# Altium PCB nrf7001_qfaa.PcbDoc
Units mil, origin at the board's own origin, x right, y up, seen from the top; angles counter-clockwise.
Board outline 738 x 600 mil, 4 copper layers (Top Layer, Mid-Layer 1, Mid-Layer 2, Bottom Layer), stack 62.315 mil thick; 22 components, 30 nets, 104 pads, 140 vias.
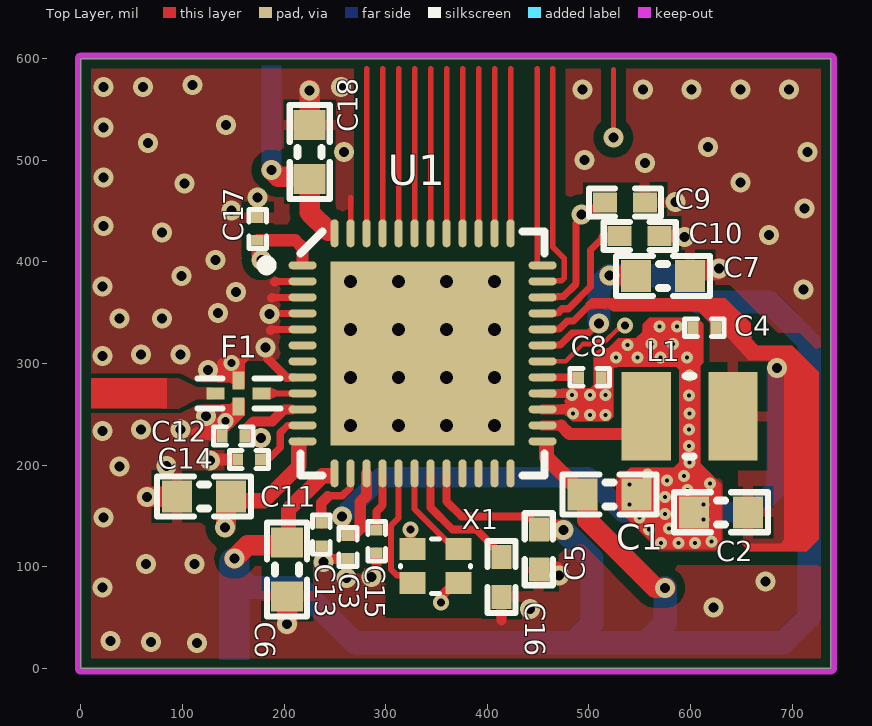
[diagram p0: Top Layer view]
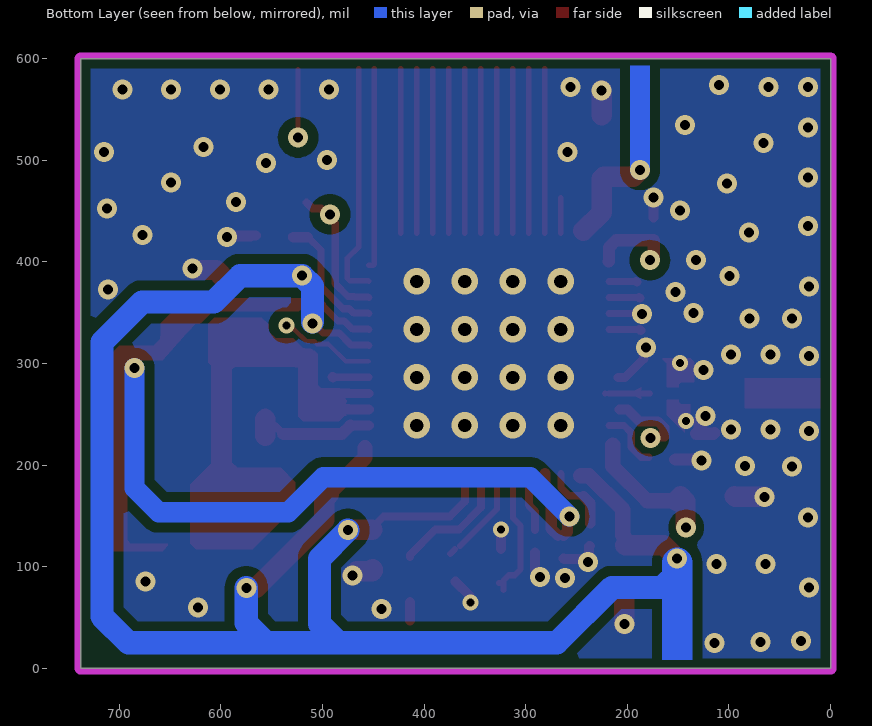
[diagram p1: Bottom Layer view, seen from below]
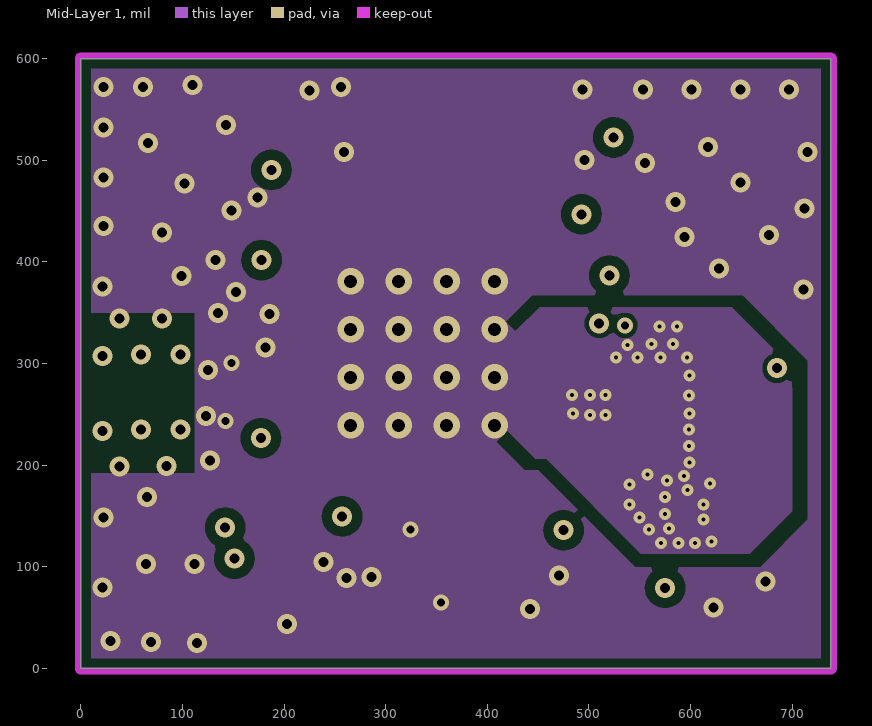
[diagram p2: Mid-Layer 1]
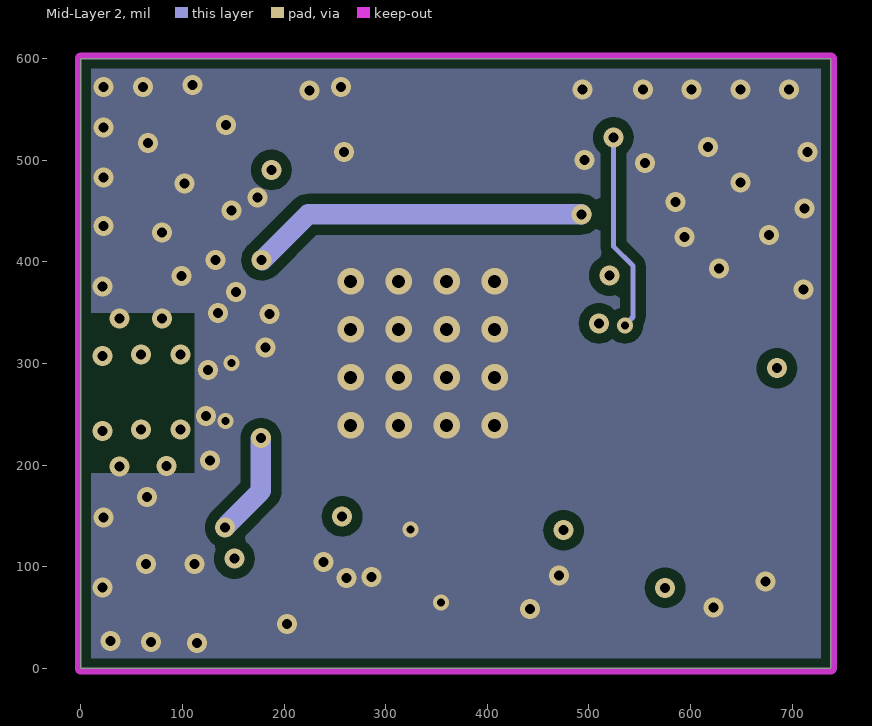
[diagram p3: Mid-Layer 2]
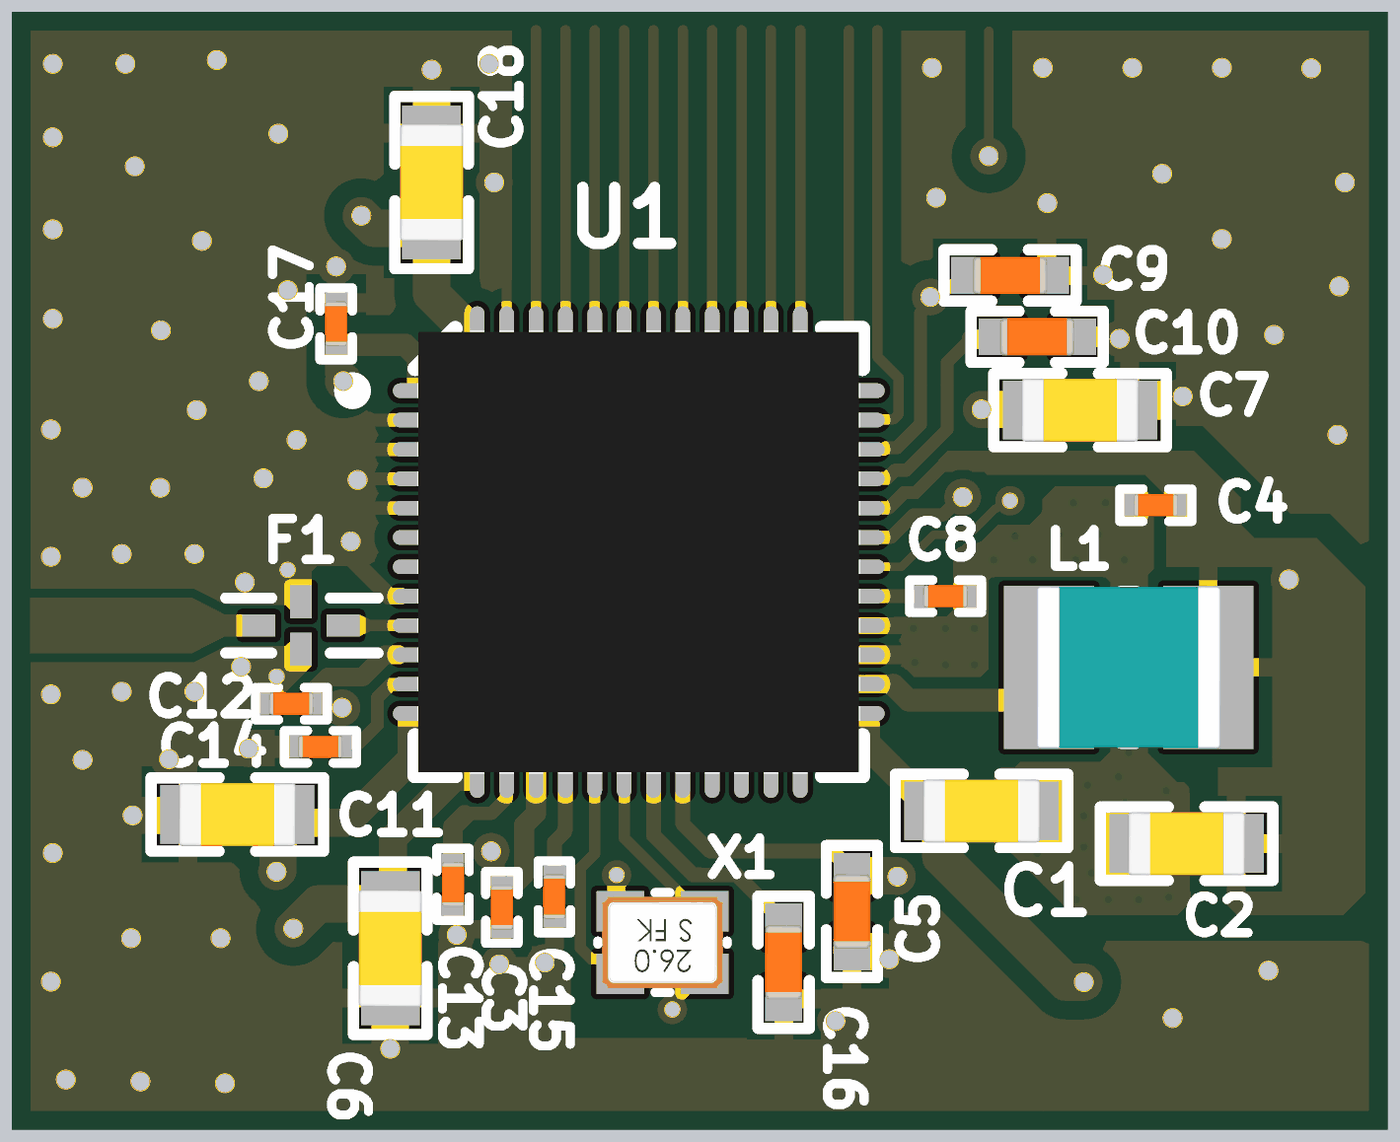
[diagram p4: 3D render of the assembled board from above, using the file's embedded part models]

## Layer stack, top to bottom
Top Solder: solder mask 1.063, Solder Resist, Dk 3.5
Top Layer: signal copper 0.689
Dielectric1: prepreg 3.5, FR-4, Dk 4.2
Mid-Layer 1: signal copper 1.378
Dielectric2: prepreg 51.1811, FR-4, Dk 4.2
Mid-Layer 2: signal copper 1.378
Dielectric3: prepreg 3.5, FR-4, Dk 4.2
Bottom Layer: signal copper 0.689
Bottom Solder: solder mask 1.063, Solder Resist, Dk 3.5

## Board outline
0,0 0,600 738,600 738,0

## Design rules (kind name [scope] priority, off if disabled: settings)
Clearance Clearance_2 [InNet('PALDO') vs OnLayer('Bottom Layer')] p1: gap=10 ignorepadtopadclearanceinfootprint=FALSE except(8: Via-Fill Via-Poly Via-Region)
Clearance Clearance_1 [InNet('ant') vs InNet('GND')] p2: gap=4.76 ignorepadtopadclearanceinfootprint=FALSE except(5: Arc-Arc Arc-Track Arc-Fill Arc-Poly Arc-Region Track-Track Track-Fill Track-Poly Track-Region SMDPad-Fill SMDPad-Poly SMDPad-Region)
Clearance Clearacnce_microvia [AsMM(ViaDiameter) = 0.3 vs AsMM(ViaDiameter) = 0.3] p3: gap=3.94 ignorepadtopadclearanceinfootprint=FALSE
Clearance Polygon_Clearance [(InNamedPolygon('Top_Layer-GND')) or (InNamedPolygon('Bottom_Layer-GND')) or (InNamedPolygon('Mid_Layer_1-GND')) or (InNamedPolygon('Mid_Layer_2-GND'))] p4: gap=10 ignorepadtopadclearanceinfootprint=FALSE except(0: Arc-Hole Track-Hole SMDPad-Hole THPad-Hole Via-Hole Fill-Hole Poly-Hole Region-Hole Text-Hole)
Clearance [All] p5: gap=4.76 ignorepadtopadclearanceinfootprint=FALSE except(5: Arc-Arc Arc-Track Track-Track)
ComponentClearance [All] p1 off: gap=10 collisioncheckmode=3 verticalgap=10 showdistances=FALSE
FabricationTestPointUsage TestPointUsage [All] p1: valid=0 allowmultiple=FALSE
FabricationTestpoint Testpoint [All] p1: side=3 testpointundercomponent=TRUE minsize=40 maxsize=100 preferedsize=60 minholesize=0 maxholesize=40 preferedholesize=32 testpointgrid=1 allowsidetop=TRUE allowsidebottom=TRUE usegrid=TRUE gridtolerance=0.01
Height [All] p1 off: minheight=0 maxheight=1000 prefheight=500
HoleSize [All] p1: absolutevalues=TRUE maxlimit=300 minlimit=3.94 maxpercent=80.000 minpercent=20.000
MinimumAnnularRing [All] p1 off: minimumring=6
PolygonConnect PolygonConnect_1 [isVia and innet(gnd)] p1: connectstyle=Direct reliefconductorwidth=10 reliefentries=4 polygonreliefangle="90 Angle" airgapwidth=10
PolygonConnect [All] p2: connectstyle=Relief reliefconductorwidth=10 reliefentries=4 polygonreliefangle="90 Angle" airgapwidth=10
RoutingVias [All] p1: holewidth=12.01 width=24 viastyle="Through Hole" minholewidth=3.94 minwidth=11.81 maxholewidth=12.01 maxwidth=24.02 useviatemplates=TRUE viatemplateguid#1={03A9E32F-EA80-447D-9B7D-60258545F035} viatemplateguid#2={9F61FF23-C90F-4B7F-A7DC-5F6911D9F630} viatemplateguid#3={EDF5FEF7-A820-4EA2-9A2F-3AF23343353B} viatemplateguid#4={47291F57-6B59-4CD3-85A7-BAD8324BE8B3} viatemplateguid#5={619015CA-C900-4F5D-A376-D984FD50A0EF} viatemplatename#1=v30h10m0 viatemplatename#2=v40h20m0mx0 viatemplatename#3=v50h25m0mx0 viatemplatename#4=v50h25m0mx0_2670034071 viatemplatename#5=v66h33m0mx0_2670034071
SilkToSolderMaskClearance SilkscreenOverComponentPads [IsPad] p1: minsilkscreentomaskgap=10 clearancetoexposedcopper=TRUE
SolderMaskExpansion [IsVia] p1: expansion=3 istentingtop=TRUE
SolderMaskExpansion SolderMaskExpansion_1 [All] p2: expansion=3 istentingtop=FALSE
SupplyNets "Schematic Supply Nets_4" [InNet('VDD_BUCK')] p1: voltage=0.000
SupplyNets "Schematic Supply Nets_3" [InNet('VBAT')] p2: voltage=0.000
SupplyNets "Schematic Supply Nets_2" [InNet('GND')] p3: voltage=0.000
SupplyNets "Schematic Supply Nets_1" [InNet('PWRIOVDD')] p4: voltage=0.000
SupplyNets "Schematic Supply Nets" [InNet('VDDIO')] p5: voltage=0.000
Width [All] p1: maxlimit=100 minlimit=4.5 preferedwidth=6 midlayer1_minwidth=4.92 midlayer4_minwidth=4.92 minimp=50.000000 maximp=50.000000 favimp=50.000000
24 further rules are at their usual default settings.

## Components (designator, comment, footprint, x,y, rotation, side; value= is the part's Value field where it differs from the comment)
C1 "4.7µF" CAPC1608X06L 520.13,171.12 r180 top
C2 "4.7µF" CAPC1608X06L 630.12,153.57 r0 top
C3 "0.22µF" CAPC0603X03L_C 262.9,119.37 r90 top
C4 "0.47µF" CAPC0603X03L_C 613.59,335.17 r0 top
C5 "1.0µF" CAPC1005X04L 450.63,117.17 r90 top
C6 "4.7µF" CAPC1608X06L 203,97.43 r90 top
C7 "2.2µF" CAPC1608X06L 573,386.21 r180 top
C8 "10nF" CAPC0603X03L_C 500.84,286.32 r0 top
C9 "2.2µF" CAPC1005X04L 535.42,458.43 r180 top
C10 "1.0µF" CAPC1005X04L 550,425.52 r0 top
C11 "4.7µF" CAPC1608X06L 121,169.26 r0 top
C12 "100nF" CAPC0603X03L_C 150,228.68 r0 top
C13 "22nF" CAPC0603X03L_C 236.64,131.71 r90 top
C14 "0.47µF" CAPC0603X03L_C 165.53,205.52 r0 top
C15 "2.2µF" CAPC0603X03L_C 291.02,125.04 r90 top
C16 "1.0µF" CAPC1005X04L 414.02,89.94 r90 top
C17 "100nF" CAPC0603X03L_C 174,432.48 r270 top
C18 "2.2µF" CAPC1608X06L 225.18,508.34 r270 top
F1 "LPF1005LL50R2400A" FILTER1005X04L-4pin 155.12,270.63 r180 top
L1 "3.3µH" INDC2520X10N 599.04,248.17 r0 top
U1 "nRF7001 QFAA" QFN40P600X600X60-48N 336.31,310 r0 top locked value=nRF7001-QFAA
X1 "40MHz" BT-XTAL_1612 349.03,100.52 r180 top

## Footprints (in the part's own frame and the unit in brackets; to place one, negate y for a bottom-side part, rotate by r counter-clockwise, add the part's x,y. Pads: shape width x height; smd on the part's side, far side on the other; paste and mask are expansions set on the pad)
BT-XTAL_1612 [mm] "Crystal 1.6 x 1.2 mm"
  rect 0.65x0.55 smd: 1(-0.575,-0.425) 2(0.575,-0.425) 3(0.575,0.425) 4(-0.575,0.425)
  silkscreen extent -0.88,-0.68 0.88,0.68, body extent -0.83,-0.63 0.83,0.63, height 0.41
CAPC0603X03L_C [mm] "Chip Capacitor, 2-Leads, Body 0.6x0.3mm, IPC High Density"
  rect 0.27x0.3 smd mask+0.05: 1(-0.285,0) 2(0.285,0)
  silkscreen extent -0.49,-0.22 0.49,0.22, body extent -0.3,-0.15 0.31,0.15, height 0.3
CAPC1005X04L [mm] "Chip Capacitor, 2-Leads, Body 1.0x0.5mm, IPC High Density"
  rect 0.6x0.5 smd: 1(-0.5,0) 2(0.5,0)
  silkscreen extent -0.9,-0.35 0.9,0.35, body extent -0.51,-0.25 0.51,0.25, height 0.5
CAPC1608X06L [mm] "Chip Capacitor, 2-Leads, Body 1.6x0.8mm, IPC High Density"
  rect 0.75x0.8 smd: 1(-0.675,0) 2(0.675,0)
  silkscreen extent -1.17,-0.5 1.17,0.5, body extent -0.8,-0.43 0.8,0.43, height 0.8
FILTER1005X04L-4pin [mm] "Filter, 4-Leads, Body 1.0x0.5mm."
  rect 0.45x0.3 smd mask+0.08: 1(-0.575,0) 3(0.575,0)
  rect 0.3x0.45 smd mask+0.08: 2(0,-0.325) 4(0,0.325)
  silkscreen extent -1.05,-0.38 1.02,0.38, body extent -0.5,-0.3 0.5,0.3, height 0.36
INDC2520X10N [mm] "Chip Inductor, 2-Leads, Body 2,50x2,00mm, IPC Medium Density"
  rect 1.23x2.22 smd: 1(-1.085,0) 2(1.085,0)
  silkscreen extent -0.1,-1.01 0.1,1.01, body extent -1.25,-1.1 1.25,1.1, height 1.98
QFN40P600X600X60-48N [mm] "QFN, 48-Leads, Body 6.1x6.1mm (max), Pitch 0.40mm, IPC Medium Density"
  oval 0.7x0.2 smd: 1(-3,2.2) 2(-3,1.8) 3(-3,1.4) 4(-3,1) 5(-3,0.6) 6(-3,0.2) 7(-3,-0.2) 8(-3,-0.6) 9(-3,-1) 10(-3,-1.4) 11(-3,-1.8) 12(-3,-2.2) 25(3,-2.2) 26(3,-1.8) 27(3,-1.4) 28(3,-1) 29(3,-0.6) 30(3,-0.2) 31(3,0.2) 32(3,0.6) 33(3,1) 34(3,1.4) 35(3,1.8) 36(3,2.2)
  oval 0.2x0.7 smd: 13(-2.2,-3) 14(-1.8,-3) 15(-1.4,-3) 16(-1,-3) 17(-0.6,-3) 18(-0.2,-3) 19(0.2,-3) 20(0.6,-3) 21(1,-3) 22(1.4,-3) 23(1.8,-3) 24(2.2,-3) 37(2.2,3) 38(1.8,3) 39(1.4,3) 40(1,3) 41(0.6,3) 42(0.2,3) 43(-0.2,3) 44(-0.6,3) 45(-1,3) 46(-1.4,3) 47(-1.8,3) 48(-2.2,3)
  rect 4.6x4.6 smd paste-5: 49(0,0)
  silkscreen extent -4.02,-3.05 3.05,3.05, body extent -3.02,-3.02 3.02,3.02, height 0.86

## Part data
C1 C2 C6 C11: library part C0603-4µ7-25V-X6S-GRM188C81E475KE11, "Capacitor, Ceramic, X6S 0603,±10%, 25V", Manufacturer=Murata, Manufacturer Part Number=GRM188C81E475KE11D, Supplier Part Number 1=490-7199-1-ND
C3: library part C0201-220n-10V-X5R-GRM033R61A224KE90, "Capacitor, Ceramic, X5R 0201, ±10%, 10V", Manufacturer=Murata, Manufacturer Part Number=GRM033R61A224KE90D, Supplier Part Number 1=81-GRM33R61A224KE90D
C4 C14: library part C0201-470n-6.3V-X5R-GRM033R60J474KE90, "Capacitor, Ceramic, X5R 0201,±10%, 6.3V", Manufacturer=Murata, Manufacturer Part Number=GRM033R60J474KE90D, Supplier Part Number 1=490-10409-1-ND
C5: library part C0402-1µ0-35V-X5R-GRM155R6YA105KE11, "Capacitor, Ceramic, X5R 0402,±10%, 35V", Manufacturer=Murata, Manufacturer Part Number=GRM155R6YA105KE11D, Supplier Part Number 1=81-GRM155R6YA105KE1D
C7 C18: library part C0603-2µ2-16V-X7S-GRM188C71C225KE11, "Capacitor, Ceramic, X7S 0603,±10%, 16V", Manufacturer=Murata, Manufacturer Part Number=GRM188C71C225KE11D, Supplier Part Number 1=81-GRM188C71C225KE1D
C8: library part C0201-10n-16V-X7R-GRM033R71C103KE14, "Capacitor, Ceramic, X7R 0201,±10%, 16V", Manufacturer=Murata, Manufacturer Part Number=GRM033R71C103KE14D, Supplier Part Number 1=490-14453-1-ND
C9: library part C0402-2µ2-25V-X5R-GRM155R61E225KE11, "Capacitor, Ceramic, X5R 0402,±10%, 25V", Manufacturer=Murata, Manufacturer Part Number=GRM155R61E225KE11D, Supplier Part Number 1=81-GRM155R61E225KE1D
C10: library part C0402-1µ0-16V-X6S-GRM155C81C105KE11D, "Capacitor, Ceramic, X6S 0402,±10%, 16V", Manufacturer=Murata, Manufacturer Part Number=GRM155C81C105KE11D, Supplier Part Number 1=490-12700-2-ND
C12 C17: library part C0201-100n-16V-X7S-GRM033C71C104KE14, "Capacitor, Ceramic, X7S 0201,±10%, 16V", Manufacturer=Murata, Manufacturer Part Number=GRM033C71C104KE14D, Supplier Part Number 1=81-GRM33C71C104KE14D
C13: library part C0201-22n-10V-X5R-GRM033R61A223KE84, "Capacitor, Ceramic, X5R 0201,±10%, 10V", Manufacturer=Murata, Manufacturer Part Number=GRM033R61A223KE84D, Supplier Part Number 1=81-GRM033R61A223KE4E
C15: library part C0201-2µ2-10V-X5R-GRM033R61A225KE47, "Capacitor, Ceramic, X5R 0201,±10%, 10V", Manufacturer=Murata, Manufacturer Part Number=GRM033R61A225KE47D, Supplier Part Number 1=81-GRM033R61A225KE7D
C16: library part C0402-1µ0-10V-X7S-GRM155C71A105KE11, "Capacitor, Ceramic, X7S 0402,±10%, 10V", Manufacturer=Murata, Manufacturer Part Number=GRM155C71A105KE11D, Supplier Part Number 1=81-GRM155C71A105KE1J
F1: "2.45GHz Center Frequency Low Pass RF Filter, 100MHz Bandwidth 0.5dB", Manufacturer=Pulse-Electronics-Corporation, Supplier Part Number 1=553-LPF1005LL50R2400ATR-ND
L1: library part L1008-3µ3-LQM2HPN3R3MGCL, "Inductor, 1A, ±20%, 200mOhm", Manufacturer=Murata, Manufacturer Part Number=LQM2HPN3R3MGCL, Supplier Part Number 1=490-12070-1-ND
U1: library part nRF7001, "Wi-Fi Single Band Companion chip", Manufacturer="Nordic Semiconductor"
X1: library part XTAL_SMD1612_40MHz_8p_40_85, "XTAL SMD 1612, 40MHz, Cl=8pF, Total Tol: ±10ppm, -40-85C", Manufacturer="Abracon Corporation", Manufacturer Part Number=ABM12W-40.0000MHZ-8-D1X-T3, Supplier Part Number 1=535-13992-1-ND

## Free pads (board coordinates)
  rrect50% 43.31x43.31 on Top Paste paste+0.49 mask+1.97: ""(275.8,369.67) ""(277.8,250.47) ""(277.8,309.52) ""(337,250.47) ""(337,309.52) ""(337,369.67) ""(396.06,250.47) ""(396.06,309.52) ""(396.06,369.67)

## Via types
v1: diameter 19.68, hole 9.84, Top Layer to Bottom Layer, tented both sides, 80 vias
v2: diameter 11.81, hole 3.94, Top Layer to Mid-Layer 1, tented top, 39 vias
v3: diameter 25.98, hole 12.99, Top Layer to Bottom Layer, tented both sides, 16 vias
v4: diameter 15.75, hole 7.87, Top Layer to Bottom Layer, tented both sides, 5 vias

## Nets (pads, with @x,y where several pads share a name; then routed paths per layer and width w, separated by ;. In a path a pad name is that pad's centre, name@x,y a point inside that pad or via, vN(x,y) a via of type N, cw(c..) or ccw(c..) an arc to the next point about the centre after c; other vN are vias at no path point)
ANT: F1.3
BUCK_EN: U1.30 | length 395
  Top Layer w4.5: U1.30 477.13,302.13 494.19,319.19 505.69,319.19 508.3,321.81 516.14,321.81 527.81,333.48 528.3,333.48 532.37,337.56 v4(535.42,337.56)
  Top Layer w4.92: v1(524,522.48) 524,589.54 524,559
  Mid-Layer 2 w4.92: v1@524,528 v1(524,522.48) 524,415.4 543.29,396.11 543.29,345.86 535.42,337.98 v4(535.42,337.56)
COEX_GRANT: U1.43 | length 161.9
  Top Layer w5.5: U1.43 328.43,590
COEX_REQ: U1.42 | length 161.9
  Top Layer w5.5: U1.42 344.18,590
COEX_STATUS: U1.41 | length 161.9
  Top Layer w5.5: U1.41 359.93,590
GND: C1.1 C2.1 C3.1 C4.1 C5.1 C6.1 C7.1 C8.2 C9.1 C10.2 C11.1 C12.1 C13.1 C14.1 C15.1 C16.1 C17.1 C18.1 F1.2 F1.4 U1.2 U1.3 U1.4 U1.5 U1.8 U1.27 U1.28 U1.47 U1.49 X1.2 X1.4 | length 651.3
  Top Layer w5.5: U1.47 265.44,463.26
  Top Layer w7: v1@186.15,349.37 U1.4 ; 187.88,333.62 U1.5 ; 188.36,365.12 U1.3 ; 191.36,380.87 U1.2
  Top Layer w9: v1(181.8,315.74) 183.84,313.7 183.84,304.75 202.22,286.38 U1.8@208.92,286.38 ; v1(185.49,348.71) v1@186.15,349.37 ; 186.81,332.56 187.88,333.62 ; 187.76,364.52 188.36,365.12 ; 190.57,380.08 191.36,380.87 ; U1.28 482.35,270.63 483.52,269.46 v2(483.52,269.04)
  Top Layer w9.84: C17.1 v1(174,463.26) ; C13.1 237.23,120.49 237.62,120.1 237.62,105.65 v1(238.64,104.63) 241.3,104.63 244.43,107.76 262.5,107.76 C3.1 ; X1.2@324.39,117.26 v4(324.39,136.78) ; v4(354.3,64.62) 355.43,65.75 355.43,71.53 X1.4@369.35,85.45 ; 414.02,47 C16.1@414.02,65.25 ; U1.27 479.65,254.88 483.77,250.76 v2(484.3,250.76) ; C10.2@565.59,426.22 v1@592.4,426.22 ; C10.2 570.21,425 593.62,425 v1(594.15,424.47)
  Top Layer w10: v1(285.9,89.8) 285.9,92.42 291.02,97.54 C15.1
  Top Layer w12: 114.34,231.58 115.12,230.81 132.38,230.81 ; v1(127,204.52) 128,205.52 C14.1@152.75,205.52
  Top Layer w20: v1(64.8,168.72) 93.89,168.72 C11.1 ; v1(203,43.52) C6.1 ; C18.1@225.18,544.47 v1(225.18,568.85) ; C5.1 450.63,95.83 450.79,95.67 466.5,95.67 v1(470.63,91.54) ; C7.1 599.57,387.2 604.34,391.96 626.39,391.96 v1(628,393.57)
  other v1: 114.34,25 69,26 29,27 441.79,58.44 622.59,60 21,79.52 674,85.45 261.55,88.82 64,102.83 112,102.83 22,148.52 38,198.52 84.34,198.89 21,233.65 59,235.11 98,235.11 123,248.48 125,293.78 21,307.52 59,308.98 98,308.98 38,344.54 79.66,344.54 135,349.56 152.75,370.16 711,373 21,375.81 99.19,386.21 132.52,401.74 677,426.52 80,429 22,435.2 148,450.52 712,452.59 585.35,458.87 102,477 649.02,478 22,483.2 555.43,497.24 495.81,500.18 258.77,508.34 715,508.34 617,513 66,517 22,532.52 143,534.52 493.55,569.85 553.02,569.85 601.02,569.85 649.02,569.85 697,569.52 22,572 61,572 256,572 110,574
  other v2: 571,123.52 588.13,123.52 604.34,123.52 620.47,124.82 559.01,136.78 579,137.82 612.6,146.26 550,148.25 575,151.69 540.15,161.13 612.6,161.13 575,168.47 597.05,175.43 540.15,181.07 619.16,181.98 576.94,185 593.59,189.43 557.87,190.8 599.04,202.43 598.59,218.64 598.59,235.02 500.84,249.52 516.31,249.52 599.04,250.76 598.59,268.43 500.84,269.04 516.31,269.04 599.04,288.11 526.7,305.78 547.59,305.83 570.59,305.78 596.73,305.83 538.13,318.42 561.59,319.43 582.59,319.43 569.46,336.43 586.59,336.43
  other v3: 265.44,239.13 312.69,239.13 359.93,239.13 407.17,239.13 265.44,286.38 312.69,286.38 359.93,286.38 407.17,286.38 265.44,333.62 312.69,333.62 359.93,333.62 407.17,333.62 265.44,380.87 312.69,380.87 359.93,380.87 407.17,380.87
  other v4: 142.09,243.28 148,300.48
IRQ: U1.46 | length 161.9
  Top Layer w5.5: U1.46 281.19,590
NetC8_1: C8.1 U1.29 | length 35.6
  Top Layer w7.5: U1.29@454.48,286.32 C8.1
  Top Layer w10: C8.1 C8.1@489.93,286.63
NetC10_1: C10.1 U1.33 | length 142.3
  Top Layer w7: U1.33 454.58,349.54 469.24,349.54 473.64,353.94 479.76,353.94 501.63,375.81 501.63,411.66 514,424.02 515.73,424.02 ; C10.1@528.82,424.02 C10.1
  Top Layer w10: 514.5,424.44 C10.1@528.4,424.44 ; 515.73,424.02 C10.1@528.82,424.02
NetC13_2: C13.2 U1.14 | length 68.8
  Top Layer w7: 242.97,169.04 243.75,169.81 257.29,169.81 265.27,177.8 265.27,191.72 U1.14
  Top Layer w10.5: C13.2 236.64,162.7 242.97,169.04
NetC15_2: C15.2 U1.16 | length 58.1
  Top Layer w8: C15.2 291.02,154.38 296.46,159.82 296.46,160.85 296.87,161.26 296.87,191.83 U1.16
NetC16_2: C16.2 U1.19 | length 124.8
  Top Layer w7.87: U1.19 344.18,158.16 365.49,136.85 369.12,136.85 369.19,136.78 388.83,136.78 414.02,111.59 C16.2
NetF1_1: F1.1 U1.9 | length 40.6
  Top Layer w6: F1.1@177.64,270.63 U1.9
NetL1_1: L1.1 U1.26 | length 132.3
  Top Layer w7.78: L1.1@538.68,230.52 L1.1
  Top Layer w10: U1.26 472.36,239.13 472.74,238.75
  Top Layer w12: 472.74,238.75 480.97,230.52 L1.1@538.68,230.52
  Top Layer w15: L1.1@556.33,245.39 L1.1
  Top Layer w20: L1.1@556.33,228.68 L1.1@556.33,245.39
NetU1_17: U1.17 X1.3 | length 133.2
  Top Layer w6: U1.17 312.69,148.12 305,140.43 305,97.43 310.81,91.62 316.6,91.62 322.01,86.21 322.01,83.79 X1.3 ; X1.3@322.01,77.11 X1.3@322.01,84.21
NetU1_18: U1.18 X1.1 | length 92.7
  Top Layer w6: U1.18 328.43,156.67 X1.1@364.64,120.47
  Top Layer w6.5: X1.1@369.67,117.26 X1.1@374.14,112.78
PALDO: C11.2 C12.2 U1.10 U1.12 | length 308.2
  Top Layer w10: v1@177.14,228 163.65,228 163.65,236.92 169.79,243.07 188.29,243.07 200.11,254.88 U1.10@207.75,254.88
  Top Layer w15: C11.2@151.94,164.89 180.41,164.89 214.42,198.89 U1.12@214.42,219.82
  Top Layer w20: v1@142.81,139.34 142.81,164.49 C11.2 C11.2@151.94,164.89
  Mid-Layer 2 w20: v1@143.8,141.12 177.12,174.44 v1@177.12,226
  other v1: 142,138.52 177.12,226.48
PWRIOVDD: C9.2 C17.2 U1.1 U1.34 | length 551.7
  Top Layer w7: U1.34 454.58,365.29 468.01,365.29 468.28,365.56 468.67,365.94 474.79,365.94 487.43,378.58 487.43,438.24 492.65,443.45 v1(492.65,446.88)
  Top Layer w8: v1(492.65,446.88) 495.81,446.88 501.52,452.59 509.89,452.59 C9.2
  Top Layer w12: v1(177.82,401.74) 177.82,402.4 174,406.21 C17.2 211.01,421.26 218.04,414.23 218.04,400.71 218.2,400.55
  Mid-Layer 2 w20: v1@178.4,401.74 223.54,446.88 v1(492.65,446.88)
QSPI_CLK/SPI_CLK: U1.35 | length 233.3
  Top Layer w5.5: U1.35 454.87,381.32 472.94,381.32 475.71,384.09 475.71,403.44 464.26,414.89 464.26,590
QSPI_DATA0/SPI_MOSI: U1.37 | length 161.9
  Top Layer w5.5: U1.37 422.92,590
QSPI_DATA1/SPI_MISO: U1.38 | length 161.9
  Top Layer w5.5: U1.38 407.17,590
QSPI_DATA2: U1.39 | length 161.9
  Top Layer w5.5: U1.39 391.42,590
QSPI_DATA3: U1.40 | length 161.9
  Top Layer w5.5: U1.40 375.68,590
QSPI_SS/SPI_SS: U1.36 | length 198.2
  Top Layer w5.5: 449,590 449,397.71 450.1,396.61 U1.36
SW_CTRL0: U1.44 | length 161.9
  Top Layer w5.5: U1.44 312.68,590
SW_CTRL1: U1.45 | length 161.9
  Top Layer w5.5: U1.45 296.94,590
SXLDO: C14.2 U1.11 | length 60.9
  Top Layer w7: C14.2@178.57,207.76 186.59,207.76 196.15,217.32 196.15,231.84 203.28,238.97 U1.11@218.03,238.97
VBAT: C1.2 C5.2 C6.2 C7.2 U1.13 U1.20 U1.25 U1.31 | length 1991.9
  Top Layer w7: U1.31 454.58,318.04 471.68,318.04 483.58,329.94 499.57,329.94 v1@505.44,335.81
  Top Layer w7.87: U1.20 359.93,164.25 374.52,149.66 439.79,149.66 C5.2@450.63,138.82
  Top Layer w15: C6.2 203,129.85 204.42,131.26 204.42,156.17 237.68,189.43 U1.13@245.76,189.43 ; 458.2,217.32 458.2,207.46 C1.2@493.55,172.1
  Top Layer w20: v1(151,108) 164.24,121.24 C6.2@202,121.24 ; C5.2@451.05,136.38 v1@474.55,136.38 ; C1.2 498.32,166.35 498.32,146.26 565.32,79.26 v1(575,79.26) ; v1(520.13,386.54) 546.1,386.54 C7.2
  Bottom Layer w23: 151,94.17 165.64,79.52 215.03,79.52 269.55,25 484,25 ; v1(475.02,135.9) 503,107.93 503,44 484,25 ; v1@509.89,341.07 509.89,376.3 v1(520.13,386.54) 580.99,386.54 607,360.52 675.68,360.52 ; v1(575,79.26) 575,44.63 555.37,25 ; 677.55,360.52 717,321.07 ; 717,319.2 717,51 691,25 555.37,25 ; 484,25 555.37,25
  Bottom Layer w30: 151,23 151,94.17 v1@151,104
  other v1: 510.02,339.52
VDD_BUCK: C2.2 C3.2 C4.2 L1.2 U1.15 U1.32 | length 764.1
  Top Layer w7: U1.32 454.58,333.79 470.46,333.79 478.61,341.94 484.83,341.94 500.51,357.63 515.73,357.63
  Top Layer w10.98: v1@258.77,147.79 v1(257.1,149.45) 257.1,147.1 256.86,146.85 257.34,146.85 258.77,145.43 258.77,134.48 262.66,130.59 C3.2 ; C3.2@268.33,130.77 274.86,137.3 274.86,163.52 281.19,169.84 U1.15 ; 611.37,355.43 622.59,344.22
  Bottom Layer w20: v1(257.1,149.45) 295.65,188 499.13,188 533.63,153.51 661.39,153.51 685,177.12 v1@685,295.52
  other v1: 685,295.35
VDDIO: C18.2 U1.48 | length 180.7
  Top Layer w20: v1(187.5,490.52) 194.24,483.76 223.18,483.76 C18.2 225.18,448.6 243.25,430.52
  Bottom Layer w20: v1(187.5,490.52) 187.5,571.17
pads on no net: U1.6 U1.7 U1.21 U1.22 U1.23 U1.24

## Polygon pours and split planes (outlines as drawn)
GND on Mid-Layer 1 "Mid_Layer_1-GND" (solid, remove dead copper, pour order 41): 0,0 0,600 738,600 738,0
GND on Mid-Layer 1 "NONET_L-01_P-001" (solid, pour order 38): 659.08,114.5 699.4,154.82 699.4,296.48 640.45,355.43 451.21,355.43 418.57,322.8 418.57,234.84 447.38,206.04 458.17,206.04 549.72,114.5
GND on Top Layer "Top_Layer-GND" (solid, remove dead copper, pour order 44): 0,0 0,600 738,600 738,0
ANT on Top Layer "NONET_L-01_P-001" (solid, pour order 45): 96.49,255.63 114.27,264.72 129.18,264.72 129.18,276.54 114.28,276.54 96.51,285.63 80.11,285.62 80.11,255.63
ANT on Top Layer "NONET_L-01_P-001" (solid, pour order 47): 96.49,255.63 114.27,264.72 129.18,264.72 129.18,276.54 114.28,276.54 96.51,285.63 80.11,285.62 80.11,255.63
GND on Top Layer "NONET_L-01_P-001" (solid, pour order 19): 472.94,249.52 475.63,249.52 482.08,243.07 519.55,243.07 524.02,247.54 524.02,295.21 525.21,296.4 586.58,296.4 589.14,293.77 589.14,202.99 583.59,197.43 540.82,197.43 525.21,181.82 525.21,160.7 568.82,117.09 624.81,117.09 630.12,122.4 630.12,181.38 624.33,187.17 624.18,187.17 609.33,202.02 609.33,298.01 609.71,298.01 612.6,300.9 612.6,339.3 606.65,345.25 559.6,345.25 552.75,338.4 552.75,331.48 546,324.73 519.88,324.73 504.74,309.59 504.74,279.1 501.17,275.52 472.94,275.52
VDD_BUCK on Top Layer "NONET_L-01_P-001" (solid, pour order 34): 710.91,111.43 726,126.52 726,291.48 699.94,317.54 681.49,317.54 681.37,317.65 666.38,317.64 659.59,324.43 659.59,339.06 634.21,364.43 542.97,364.43 497,364.43 497,353.02 521.66,353.02 523.25,351.43 607.59,351.43 619.16,339.86 619.16,309.77 619.19,309.74 619.16,309.71 619.16,205.16 643.89,180.43 643.89,128.78 661.24,111.43
GND on Bottom Layer "Bottom_Layer-GND" (solid, remove dead copper, pour order 6): 0,0 0,600 738,600 738,0
GND on Mid-Layer 2 "Mid_Layer_2-GND" (solid, remove dead copper, pour order 43): 0,0 0,600 735,600 735,0

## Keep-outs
Keep-Out Layer:
  lines w6: -3,-0.09 -3,599.91 ; 0,-3 cw(c0,0) -3,0 ccw(c0,0) 0,-3 ; 0,-3 738,-3 ; 0,603 ccw(c0,600) -3,600 cw(c0,600) 0,603 ; 0,603 738,603 ; 738,-3 ccw(c738,0) 741,0 ; 738,-3 ccw(c738,0) 741,0 ; 738,603 cw(c738,600) 741,600 ; 738,603 cw(c738,600) 741,600 ; 741,0 741,600

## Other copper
Top Layer:
  rectangle net GND: 121,235.2 135,246.98
  rectangle net ANT: 9.94,255.62 84.49,285.62
  pour cut-out: 147.68,302.48 190.2,302.48 208.55,284.14 208.55,260.7 193.24,245.39 147.68,245.39
  region net GND: 138.1,238.68 139.8,238.68 148.5,247.38 148.2,247.68 138.1,247.68
  region net GND: 152.83,240.78 143.7,231.65 143.7,240.78
  region net GND: 138.78,238.68 150.7,238.68 161.01,248.98 161.01,249.52 146.85,249.52 138.78,241.46
  region net GND: 161,299.59 165.12,303.7 165.12,305.18 159.87,305.18 137.5,305.18 134.2,301.88 134.2,281.58 146.7,281.58 149.2,279.08 149.19,276.54 161.01,276.54
  region net GND: 138.3,259.68 146.7,259.68 149.2,262.18 149.2,264.58 161,264.58 161.01,248.98 158.3,246.28 138.3,246.28
  region net GND: 526.7,183.32 540.82,197.43 583.58,197.43 589.14,202.98 589.14,293.79 586.03,296.9 527.34,296.9 527.34,296.4 525.21,296.4 524.02,295.21 524.02,247.54 519.55,243.07 483.7,243.07 480.15,246.6 479.09,247.5 477.64,248.38 476.8,248.72 477.3,249.97 472.94,249.99 472.93,259.8 477.3,259.8 476.7,261.26 475.78,262.75 476.72,264.3 477.48,266.13 472.95,266.15 472.91,275.17 481.91,275.13 482.56,275.53 501.17,275.52 504.74,279.1 504.74,309.57 507.6,312.43 508.36,312.66 509.7,313.37 510.62,314.13 511.25,314.76 516.37,314.76 517.33,314.85 518.88,315.31 520.07,315.95 521.09,316.81 529.02,324.73 546,324.73 552.76,331.48 552.75,338.41 559.6,345.25 606.65,345.25 612.6,339.31 612.6,300.89 609.72,298.01 609.33,298.01 609.32,202.01 630.12,181.37 630.13,122.4 624.8,117.08 568.81,117.09 526.69,159.22
  region net VDD_BUCK: 700.99,115.3 657.39,115.33 652.28,120.5 652.28,123.01 689.08,122.84 692.26,126.96 692.43,295.05 684.74,303.01 657.06,303 633.89,329.53 612.78,351.58 607.59,351.43 523.24,351.43 521.66,353.02 518.64,356 496.99,355.98 496.99,359.26 502.17,364.43 634.21,364.43 659.22,339.42 659.22,327.13 659.58,326.76 659.59,324.43 666.37,317.64 681.37,317.65 681.49,317.54 699.94,317.54 726.01,291.48 726,127 714.3,115.3
  pour cut-out: 438,345.22 481.7,345.22 502.36,365.88 540.17,365.88 634.46,365.88 659.22,341.13 659.21,327.12 665.91,320.43 700.78,320.43 726,295.22 726,127 714.3,115.3 569.13,115.3 526.7,157.74 526.7,196.52 493.58,229.64 442.78,229.64 429.25,229.64 429.25,218.52 448.1,218.36 565.03,101.43 687.92,101.43 723.83,101.43 738,115.61 738,299.42 711.99,325.43 706.92,330.5 685.65,330.5 638.46,377.69 631.73,377.69 544.22,377.69 501.17,377.69 479.1,355.63 438,355.63
  pour cut-out: 299.72,62.25 299.72,148.66 399,148.66 399,49.36 299.72,49.36
  pour cut-out: 615.15,196.52 625.15,186.52 629,186.52 629,195.52 628,196.52
  pour cut-out: 444,355.52 434.73,355.52 426.86,347.65 426.86,219.32 426.18,218.64 444.39,218.64 444.39,227.83 440.79,231.44 440.79,345.43 444.39,345.43 444.39,355.43
  pour cut-out: 621.01,110.55 632.44,122.82 632.44,204.46 647,204.46 647,119.07 655.42,110.65 655.42,101.31 621.01,101.31
Mid-Layer 1:
  pour cut-out: -3.22,349.75 112,349.7 112,191.78 -1.94,191.78
  pour cut-out: 409.23,223.15 419.72,233.64 447.83,205.52 458,205.52 551.11,112.42 658.38,112.42 700.65,154.69 700.65,295.23 640.36,355.52 450,355.52 450,366.53 651.26,366.53 715,302.79 715,146.62 668.45,100.08 545.45,100.08 450,195.52 436.86,195.52
  pour cut-out: 453,366.52 444,366.52 418.54,341.07 427.09,332.52 428.49,332.52 451.49,355.52 453,355.52
Mid-Layer 2:
  pour cut-out: -3.22,349.75 112,349.7 112,191.78 -1.94,191.78
Bottom Layer:
  rectangle net VDDIO: 177.5,569.88 197.5,593.36
  rectangle net VBAT: 136,8 166,36

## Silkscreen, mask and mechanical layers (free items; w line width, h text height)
Board Outline:
  the board outline again, w6
Top Top Impedance Info:
  rectangle: 9.98,255.62 57.52,285.62
  lines w4: 51.54,226.74 51.54,250.77 47.18,246.41 56.17,246.41 52,250.58 ; 143.22,-20.17 159.92,-20.17 ; 144.42,-18.87 151.82,-11.47 ; 152.52,-44.97 152.52,-20.17 ; 152.52,-11.97 160.72,-20.17 ; 181.09,621.58 189.29,613.38 ; 181.89,621.58 198.59,621.58 ; 189.29,621.58 189.29,646.38 ; 189.99,612.88 197.39,620.28 ; 208.05,278.89 208.05,320.66 202.94,315.55 214.11,315.55 208.52,321.14
  lines w6: 188.83,270.63 213.25,270.63
  lines w30: 53.41,270.62 92.41,270.62
  text "Feed IOVDD here" at 84.91,657.18 h25
  text "50 ohm  / Microstrip" at 121.59,300.61 h30
  text "50 ohm  / co-planar" at 2.62,71.19 h30
  text "Feed VBAT here" at 45.38,-79.05 h25
Top Via Capping:
  circle w3.94: c612.6,161.13 r1.68
  circle w3.94: c575,168.47 r1.68
  circle w3.94: c597.05,175.43 r1.68
  circle w3.94: c619.16,181.98 r1.68
  circle w3.94: c576.94,185 r1.68
  circle w3.94: c547.59,305.83 r1.68
  circle w3.94: c557.87,190.8 r1.68
  circle w3.94: c570.59,305.78 r1.68
  circle w3.94: c593.59,189.43 r1.68
  circle w3.94: c596.73,305.83 r1.68
  circle w3.94: c598.59,218.64 r1.68
  circle w3.94: c598.59,235.02 r1.68
  circle w3.94: c598.59,268.43 r1.68
  circle w3.94: c599.04,202.43 r1.68
  circle w3.94: c599.04,250.76 r1.68
  circle w3.94: c599.04,288.11 r1.68
  circle w3.94: c569.46,336.43 r1.68
  circle w3.94: c586.59,336.43 r1.68
  circle w3.94: c526.7,305.78 r1.68
  circle w3.94: c538.13,318.42 r1.68
  circle w3.94: c561.59,319.43 r1.68
  circle w3.94: c582.59,319.43 r1.68
  circle w3.94: c500.84,249.52 r1.68
  circle w3.94: c500.84,269.04 r1.68
  circle w3.94: c516.31,269.04 r1.68
  circle w3.94: c483.52,269.04 r1.68
  circle w3.94: c484.3,250.76 r1.68
  circle w3.94: c516.31,249.52 r1.68
  circle w3.94: c579,137.82 r1.68
  circle w3.94: c575,151.69 r1.68
  circle w3.94: c571,123.52 r1.68
  circle w3.94: c588.13,123.52 r1.68
  circle w3.94: c620.47,124.82 r1.68
  circle w3.94: c604.34,123.52 r1.68
  circle w3.94: c612.6,146.26 r1.68
  circle w3.94: c559.01,136.78 r1.68
  circle w3.94: c550,148.25 r1.68
  circle w3.94: c540.15,161.13 r1.68
  circle w3.94: c540.15,181.07 r1.68

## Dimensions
738,0 to 738,600 on Dimension
0,0 to 738,0 on Dimension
